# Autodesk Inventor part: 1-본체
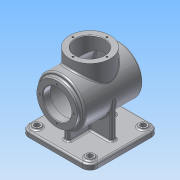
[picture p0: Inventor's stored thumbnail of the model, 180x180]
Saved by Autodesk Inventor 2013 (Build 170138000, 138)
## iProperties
Created: 2015-07
Part Number: 1-본체
Material: 알루미늄 6061
Document SubType Name: Modeling
Designer: Administrator
Density: 2.71 g/cm^3
Mass: 1277.74 g
Surface Area: 1267.64 cm^2
Volume: 471.49 cm^3
Author: Administrator
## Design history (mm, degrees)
sketch "스케치1"
  geometry: C1 r 45 at (0, 0); 1 further point
  constraints: 1 centre point, 1 coincident
  dimensions: "d0" = 90 diameter of C1
extrude "돌출1" new body sketch "스케치1" stored distance "d2" = 110; taper "d3" = 0 deg
node "작업 평면1"
sketch "스케치2"
  geometry: L1 (-50, 65)-(50, 65); L2 (65, 50)-(65, -50); L3 (50, -65)-(-50, -65); L4 (-65, -50)-(-65, 50); A1 r 15 centre (-50, 50) between (-50, 65) and (-65, 50); A2 r 15 centre (50, 50) between (65, 50) and (50, 65); A3 r 15 centre (50, -50) between (50, -65) and (65, -50); A4 r 15 centre (-50, -50) between (-65, -50) and (-50, -65); 2 further points
  constraints: 8 end point, 8 point on circle, 8 tangent, 4 centre point, 3 equal radius, 2 parallel, 2 perpendicular, 1 horizontal, 1 midpoint, 1 vertical alignment
  dimensions: "d5" = 65 distance from line of L3 point (0, 0); "d6" = 65 distance from line of L1 point (0, 0); "d7" = 15 radius of A1
extrude "돌출2" join sketch "스케치2" distance "d8" = 10; taper "d9" = 0 deg
sketch "스케치3"
  geometry: L1 (-78, 50)-(-78, 65) reference; L2 (-78, -50)-(-78, 50) reference; L3 (-78, -65)-(-78, -50) reference; L4 (-68, 50)-(-68, 65) reference; L5 (-68, -50)-(-68, 50) reference; L6 (-68, -65)-(-68, -50) reference; L7 (0, 45)-(-68, 45); L8 (0, -45)-(-68, -45); A1 r 45 centre (0, 0) between (0, 45) and (0, -45) reference; 1 further point
  constraints: 4 end point, 2 perpendicular, 2 point on circle, 2 point on line, 2 tangent
extrude "돌출3" join sketch "스케치3" stored distance "d10" = 10; taper "d11" = 0 deg
sketch "스케치4"
  geometry: L1 (68, -50)-(68, -65) reference; L2 (68, 65)-(68, 50) reference; L3 (68, 50)-(68, -50) reference; L4 (45, -55)-(45, 55) reference; L5 (68, 45)-(18, 45); L6 (18, 45)-(18, -45); L7 (18, -45)-(68, -45); 2 further points
  constraints: 6 end point, 3 perpendicular, 2 point on line, 1 horizontal alignment, 1 midpoint
  dimensions: "d12" = 90 distance between parallel lines of L7 L5; "d14" = 50 distance between parallel lines of L3 L6
extrude "돌출4" join sketch "스케치4" stored distance "d15" = 10; taper "d16" = 0 deg
sketch "스케치5"
  geometry: C1 r 38 at (0, 0); 1 further point
  constraints: 1 centre point, 1 coincident
  dimensions: "d17" = 76 diameter of C1
extrude "돌출5" join sketch "스케치5" distance "d19" = 62; taper "d20" = 0 deg
sketch "스케치6"
  geometry: C1 r 38 at (0, 0); 1 further point
  constraints: 1 centre point, 1 coincident
  dimensions: "d21" = 76 diameter of C1
extrude "돌출6" join sketch "스케치6" distance "d23" = 7; taper "d24" = 0 deg
sketch "스케치7"
  geometry: L1 (-50, 50)-(50, 50); L2 (50, 50)-(50, -50); L3 (50, -50)-(-50, -50); L4 (-50, -50)-(-50, 50); C1 r 7.5 at (-50, 50); C2 r 7.5 at (50, 50); C3 r 7.5 at (50, -50); C4 r 7.5 at (-50, -50); 3 further points
  constraints: 8 end point, 4 centre point, 4 coincident, 3 equal radius, 2 midpoint, 2 parallel, 1 horizontal, 1 horizontal alignment, 1 perpendicular, 1 vertical alignment
  dimensions: "d25" = 100 distance of L1.start L1.end; "d27" = 100 distance of L1.end L2.end; "d28" = 15 diameter of C2
extrude "돌출7" join sketch "스케치7" distance "d29" = 3; taper "d30" = 0 deg
hole "구멍1" diameter "d33" = 10; stored, may be unused: countersink angle "d37" = 90 deg, drill point angle "d39" = 118 deg; dims "d31" = 10, "d32" = 10, "d34" = 6, "d35" = 4, "d36" = 2, "d38" = 8
hole "구멍2" diameter "d42" = 10; stored, may be unused: countersink angle "d46" = 90 deg, drill point angle "d48" = 118 deg; dims "d40" = 10, "d41" = 10, "d43" = 6, "d44" = 4, "d45" = 2, "d47" = 8
hole "구멍3" diameter "d51" = 10; stored, may be unused: countersink angle "d55" = 90 deg, drill point angle "d57" = 118 deg; dims "d49" = 10, "d50" = 10, "d52" = 6, "d53" = 4, "d54" = 2, "d56" = 8
hole "구멍4" diameter "d60" = 10; stored, may be unused: countersink angle "d64" = 90 deg, drill point angle "d66" = 118 deg; dims "d58" = 10, "d59" = 10, "d61" = 6, "d62" = 4, "d63" = 2, "d65" = 8
sketch "스케치8"
  geometry: L1 (-45, -55)-(45, -55) reference; L2 (38, 62)-(-38, 62) reference; L3 (0, -55)-(0, 62); L4 (0, -48)-(-40, -48); L5 (-40, -48)-(-40, 48); L6 (-40, 48)-(-27, 48); L7 (-27, 48)-(-27, 62); 1 further point
  constraints: 10 end point, 3 perpendicular, 2 midpoint, 2 point on line, 1 parallel, 1 vertical
  dimensions: "d67" = 14 distance of L6.end L7.end; "d69" = 7 distance between parallel lines of L1 L4; "d70" = 80 diameter of L5 L3; "d71" = 54 diameter of L7 L3
revolve "회전1" sketch "스케치8" stored, may be unused: angle "d72" = 90 deg
hole "구멍5" diameter "d75" = 54; stored, may be unused: countersink angle "d79" = 90 deg, drill point angle "d81" = 118 deg; dims "d73" = 10, "d74" = 10, "d76" = 6, "d77" = 4, "d78" = 2, "d80" = 50
sketch "스케치10"
  geometry: 2 further points
  constraints: 1 vertical alignment
  dimensions: "d82" = 32 distance of point (0, 0) point (0, 32)
hole "구멍6" sketch "스케치10" at (0, 32) diameter "d83" = 3.242; stored, may be unused: countersink angle "d87" = 90 deg, drill point angle "d89" = 118 deg; dims "d84" = 8, "d85" = 4, "d86" = 2, "d88" = 10
sketch "스케치11"
  geometry: 2 further points
  constraints: 1 horizontal alignment
  dimensions: "d93" = 32 distance of point (32, 0) point (0, 0)
hole "구멍7" sketch "스케치11" at (32, 0) diameter "d94" = 3.242; stored, may be unused: countersink angle "d98" = 90 deg, drill point angle "d100" = 118 deg; dims "d95" = 8, "d96" = 4, "d97" = 2, "d99" = 10
sketch "스케치12"
  geometry: L1 (-3.602, -24.887)-(-3.602, 24.887); L2 (-3.602, 24.887)-(3.602, 24.887); L3 (3.602, 24.887)-(3.602, -24.887); L4 (3.602, -24.887)-(-3.602, -24.887); 4 further points
  constraints: 2 midpoint, 1 coincident, 1 horizontal alignment, 1 vertical, 1 vertical alignment, 2 other
  dimensions: "d104" = 7.20489 distance between parallel lines of L3 L1; "d105" = 49.77477 distance between parallel lines of L4 L2
feature "엠보싱1" sketch "스케치12" dims "d0" = 90, "d106" = 0.5, "d107" = 0
chamfer "모따기1" distance "d108" = 1; stored, may be unused: second distance "d109" = 2, angle "d110" = 45 deg
chamfer "모따기2" distance "d111" = 1; stored, may be unused: second distance "d112" = 2, angle "d113" = 45 deg
fillet "모깎기1" dims "d114" = 3
fillet "모깎기2" dims "d115" = 3
fillet "모깎기3" dims "d116" = 3
fillet "모깎기4" dims "d117" = 3
fillet "모깎기5" dims "d118" = 3
fillet "모깎기6" dims "d119" = 3
fillet "모깎기7" dims "d120" = 3
fillet "모깎기8" dims "d121" = 3
fillet "모깎기9" dims "d122" = 3
fillet "모깎기10" dims "d123" = 3
node "솔리드1"
pattern_circular "원형 패턴1" dims angle "d91" = 360 deg
pattern_circular "원형 패턴2" dims angle "d102" = 360 deg
other parameters: "d4" = -78
